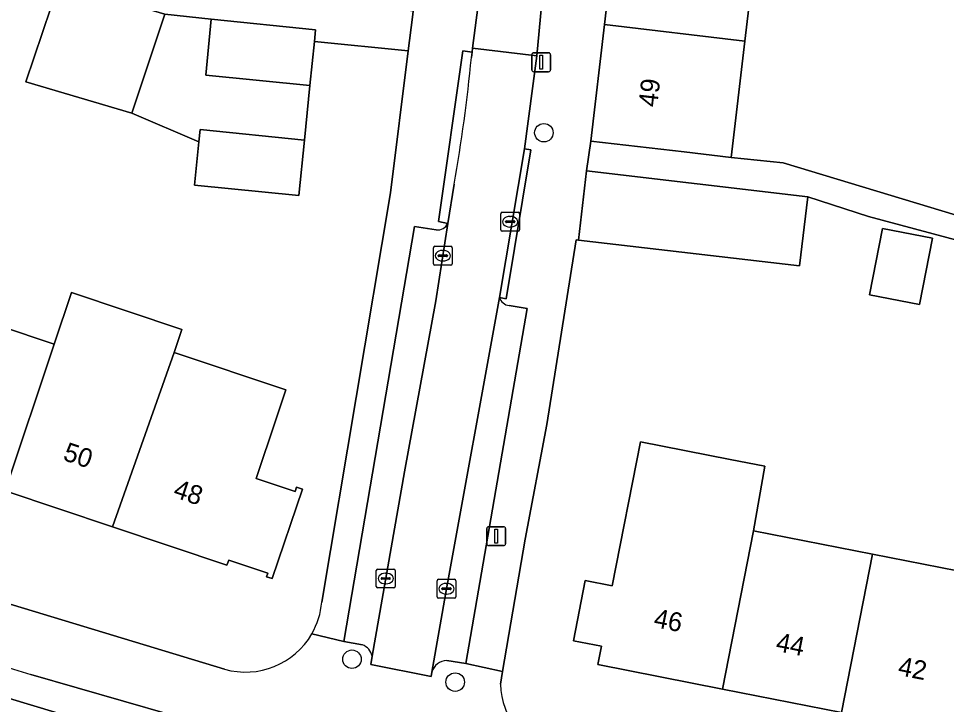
# Model space of a CAD drawing. Extents: x 161692 to 162379, y 380760 to 381678.
# Drawn here: x 162049.01 to 162098.13, y 380945.92 to 380982.23 of the extents above; entities that cross this region are included whole.
import ezdxf

# ---------------------------------------------------------------- set-up
doc = ezdxf.new("R2010")
doc.units = 0
for name, color, linetype in [('IMGEO_Boom', 7, 'Continuous'), ('IMGEO_Erf', 7, 'Continuous'), ('IMGEO_Kolk', 7, 'Continuous'), ('IMGEO_Lichtmast', 7, 'Continuous'), ('IMGEO_Pand', 7, 'Continuous'), ('IMGEO_Pand_nummerreeks', 7, 'Continuous'), ('IMGEO_Parkeervlak_open', 7, 'Continuous'), ('IMGEO_Rijbaan_lokaal_open', 7, 'Continuous'), ('IMGEO_Voetpad_open', 7, 'Continuous')]:
    doc.layers.add(name, color=color, linetype=linetype)

msp = doc.modelspace()

# ---------------------------------------------------------------- linework, layer by layer
at = {"layer": 'IMGEO_Boom'}
for centre in [(162076.818, 380976.189), (162066.662, 380948.318), (162072.124, 380947.104)]:
    msp.add_circle(centre, 0.489, dxfattribs=at)
at = {"layer": 'IMGEO_Erf'}
for points in [[(162108.948, 380996.227), (162092.107, 380998.166), (162091.414, 380992.247), (162092.261, 380992.148), (162091.592, 380986.443), (162088.137, 380986.847), (162087.458, 380981.041), (162086.737, 380974.878), (162089.487, 380974.589), (162100.749, 380971.183), (162102.141, 380971.158), (162102.669, 380975.748), (162102.837, 380975.728), (162102.984, 380975.711), (162103.382, 380979.175), (162103.236, 380979.192), (162103.592, 380982.285), (162107.294, 380981.859)], [(162094.057, 380967.607), (162094.745, 380971.12), (162097.388, 380970.603), (162096.7, 380967.089)]]:
    msp.add_lwpolyline(points, close=True, dxfattribs=at)
for points in [[(162058.561, 380975.708), (162055.003, 380977.223), (162049.4, 380978.891), (162051.158, 380984.129), (162042.064, 380986.765), (162028.946, 380990.739), (162028.64, 380987.79), (162028.341, 380984.905), (162028.036, 380981.959), (162022.566, 380982.526), (162022.872, 380985.472), (162023.171, 380988.357), (162023.436, 380990.915), (162015.772, 380991.71), (162013.002, 380966.811)], [(162065.061, 380951.346), (162068.692, 380973.013), (162069.64, 380980.521), (162064.673, 380981.023), (162064.437, 380978.687), (162064.146, 380975.802), (162063.848, 380972.857), (162058.33, 380973.414), (162058.561, 380975.708)], [(162132.879, 380959.696), (162133.289, 380963.379), (162133.292, 380963.402), (162128.302, 380963.957), (162127.875, 380960.276), (162121.451, 380961.021), (162118.709, 380961.339), (162119.137, 380965.021), (162094.009, 380971.754), (162090.784, 380972.802), (162090.355, 380969.134), (162078.65, 380970.503), (162078.529, 380970.519), (162076.983, 380960.751), (162075.837, 380954.674), (162074.633, 380947.67), (162074.517, 380946.993)], [(162045.148, 380966.92), (162050.899, 380964.99), (162051.819, 380967.732), (162057.652, 380965.775), (162057.243, 380964.561), (162063.159, 380962.576), (162062.646, 380961.048), (162061.584, 380957.882), (162063.652, 380957.188), (162063.731, 380957.425), (162064.034, 380957.323), (162062.444, 380952.582), (162062.14, 380952.683), (162062.203, 380952.872), (162060.135, 380953.565), (162060.043, 380953.29), (162053.992, 380955.32), (162048.296, 380957.232)], [(162016.411, 380962.617), (162029.526, 380957.667), (162046.576, 380951.828), (162059.92, 380947.792)], [(162092.574, 380945.498), (162086.277, 380946.738), (162079.678, 380948.037), (162079.861, 380949.008), (162078.391, 380949.288), (162079.005, 380952.476), (162080.435, 380952.204), (162081.93, 380959.823), (162086.682, 380958.89), (162088.516, 380958.53), (162087.919, 380955.109), (162094.217, 380953.873), (162100.51, 380952.638)]]:
    msp.add_lwpolyline(points, dxfattribs=at)
for centre, radius, start, end in [((162061.035, 380951.675), 4.04, 330.1077, 355.3238), ((162061.035, 380951.674), 4.039, 253.9792, 330.1192), ((162078.598, 380947.117), 4.083, 181.7446, 253.9573)]:
    msp.add_arc(centre, radius, start, end, dxfattribs=at)
at = {"layer": 'IMGEO_Kolk'}
for p, q in [((162074.535, 380971.051), (162074.535, 380971.903)), ((162074.61, 380971.977), (162075.462, 380971.977)), ((162075.536, 380971.903), (162075.536, 380971.051)), ((162074.794, 380971.471), (162074.794, 380971.483)), ((162075.232, 380971.434), (162074.834, 380971.434)), ((162074.837, 380971.52), (162075.235, 380971.52)), ((162075.023, 380971.757), (162075.048, 380971.757)), ((162075.278, 380971.483), (162075.278, 380971.471)), ((162075.462, 380970.977), (162074.61, 380970.977)), ((162075.046, 380971.197), (162075.021, 380971.197)), ((162070.968, 380969.252), (162070.968, 380970.104)), ((162071.043, 380970.178), (162071.895, 380970.178)), ((162071.456, 380969.958), (162071.481, 380969.958)), ((162071.969, 380970.104), (162071.969, 380969.252)), ((162071.227, 380969.672), (162071.227, 380969.684)), ((162071.665, 380969.635), (162071.267, 380969.635)), ((162071.27, 380969.721), (162071.668, 380969.721)), ((162071.479, 380969.398), (162071.454, 380969.398)), ((162071.711, 380969.684), (162071.711, 380969.672)), ((162071.895, 380969.178), (162071.043, 380969.178)), ((162067.949, 380952.164), (162067.949, 380953.016)), ((162068.024, 380953.09), (162068.876, 380953.09)), ((162068.437, 380952.87), (162068.462, 380952.87)), ((162068.95, 380953.016), (162068.95, 380952.164)), ((162068.208, 380952.584), (162068.208, 380952.596)), ((162068.646, 380952.547), (162068.248, 380952.547)), ((162068.251, 380952.633), (162068.649, 380952.633)), ((162068.46, 380952.31), (162068.435, 380952.31)), ((162068.692, 380952.596), (162068.692, 380952.584)), ((162071.162, 380951.622), (162071.162, 380952.474)), ((162071.237, 380952.548), (162072.089, 380952.548)), ((162071.65, 380952.328), (162071.675, 380952.328)), ((162072.163, 380952.474), (162072.163, 380951.622)), ((162068.876, 380952.09), (162068.024, 380952.09)), ((162071.421, 380952.042), (162071.421, 380952.054)), ((162071.859, 380952.005), (162071.461, 380952.005)), ((162071.464, 380952.091), (162071.862, 380952.091)), ((162071.673, 380951.768), (162071.648, 380951.768)), ((162071.905, 380952.054), (162071.905, 380952.042)), ((162072.089, 380951.548), (162071.237, 380951.548))]:
    msp.add_line(p, q, dxfattribs=at)
for points in [[(162074.535, 380971.051), (162074.535, 380971.903)], [(162074.61, 380971.977), (162075.462, 380971.977)], [(162075.536, 380971.903), (162075.536, 380971.051)], [(162075.462, 380970.977), (162074.61, 380970.977)], [(162070.968, 380969.252), (162070.968, 380970.104)], [(162071.043, 380970.178), (162071.895, 380970.178)], [(162071.969, 380970.104), (162071.969, 380969.252)], [(162071.895, 380969.178), (162071.043, 380969.178)], [(162067.949, 380952.164), (162067.949, 380953.016)], [(162068.024, 380953.09), (162068.876, 380953.09)], [(162068.95, 380953.016), (162068.95, 380952.164)], [(162071.162, 380951.622), (162071.162, 380952.474)], [(162071.237, 380952.548), (162072.089, 380952.548)], [(162072.163, 380952.474), (162072.163, 380951.622)], [(162068.876, 380952.09), (162068.024, 380952.09)], [(162072.089, 380951.548), (162071.237, 380951.548)]]:
    msp.add_lwpolyline(points, dxfattribs=at)
for centre, radius, start, end in [((162074.612, 380971.901), 0.0765, 91.552, 178.448), ((162074.612, 380971.901), 0.0765, 91.552, 178.448), ((162075.46, 380971.901), 0.0765, 1.552, 88.448), ((162075.46, 380971.901), 0.0765, 1.552, 88.448), ((162074.834, 380971.48), 0.0403, 85.8775, 175.7526), ((162074.831, 380971.47), 0.0366, 178.938, 274.7102), ((162075.235, 380971.477), 0.043, 264.8664, 352.4533), ((162075.239, 380971.482), 0.0386, 1.7309, 96.639), ((162074.612, 380971.053), 0.0765, 181.552, 268.448), ((162074.612, 380971.053), 0.0765, 181.552, 268.448), ((162075.46, 380971.053), 0.0765, 271.552, 358.448), ((162075.46, 380971.053), 0.0765, 271.552, 358.448), ((162071.045, 380970.102), 0.0765, 91.552, 178.448), ((162071.045, 380970.102), 0.0765, 91.552, 178.448), ((162071.893, 380970.102), 0.0765, 1.552, 88.448), ((162071.893, 380970.102), 0.0765, 1.552, 88.448), ((162071.267, 380969.681), 0.0403, 85.8775, 175.7526), ((162071.264, 380969.671), 0.0366, 178.938, 274.7102), ((162071.668, 380969.678), 0.043, 264.8664, 352.4533), ((162071.672, 380969.683), 0.0386, 1.7309, 96.639), ((162071.045, 380969.254), 0.0765, 181.552, 268.448), ((162071.045, 380969.254), 0.0765, 181.552, 268.448), ((162071.893, 380969.254), 0.0765, 271.552, 358.448), ((162071.893, 380969.254), 0.0765, 271.552, 358.448), ((162068.026, 380953.014), 0.0765, 91.552, 178.448), ((162068.026, 380953.014), 0.0765, 91.552, 178.448), ((162068.874, 380953.014), 0.0765, 1.552, 88.448), ((162068.874, 380953.014), 0.0765, 1.552, 88.448), ((162068.026, 380952.166), 0.0765, 181.552, 268.448), ((162068.026, 380952.166), 0.0765, 181.552, 268.448), ((162068.248, 380952.593), 0.0403, 85.8775, 175.7526), ((162068.245, 380952.583), 0.0366, 178.938, 274.7102), ((162068.649, 380952.59), 0.043, 264.8664, 352.4533), ((162068.653, 380952.595), 0.0386, 1.7309, 96.639), ((162068.874, 380952.166), 0.0765, 271.552, 358.448), ((162068.874, 380952.166), 0.0765, 271.552, 358.448), ((162071.239, 380952.472), 0.0765, 91.552, 178.448), ((162071.239, 380952.472), 0.0765, 91.552, 178.448), ((162072.087, 380952.472), 0.0765, 1.552, 88.448), ((162072.087, 380952.472), 0.0765, 1.552, 88.448), ((162071.461, 380952.051), 0.0403, 85.8775, 175.7526), ((162071.458, 380952.041), 0.0366, 178.938, 274.7102), ((162071.862, 380952.048), 0.043, 264.8664, 352.4533), ((162071.866, 380952.053), 0.0386, 1.7309, 96.639), ((162071.239, 380951.624), 0.0765, 181.552, 268.448), ((162071.239, 380951.624), 0.0765, 181.552, 268.448), ((162072.087, 380951.624), 0.0765, 271.552, 358.448), ((162072.087, 380951.624), 0.0765, 271.552, 358.448)]:
    msp.add_arc(centre, radius, start, end, dxfattribs=at)
for centre, major_axis, ratio, start_param, end_param in [((162075.022, 380971.477), (-0.387, 0.002), 0.722429, 4.712389, 7.853982), ((162075.047, 380971.477), (-0.39, 0.002), 0.717154, 1.570796, 4.712389), ((162071.455, 380969.678), (-0.387, 0.002), 0.722429, 4.712389, 7.853982), ((162071.48, 380969.678), (-0.39, 0.002), 0.717154, 1.570796, 4.712389), ((162068.436, 380952.59), (-0.387, 0.002), 0.722429, 4.712389, 7.853982), ((162068.461, 380952.59), (-0.39, 0.002), 0.717154, 1.570796, 4.712389), ((162071.649, 380952.048), (-0.387, 0.002), 0.722429, 4.712389, 7.853982), ((162071.674, 380952.048), (-0.39, 0.002), 0.717154, 1.570796, 4.712389)]:
    msp.add_ellipse(centre, major_axis=major_axis, ratio=ratio, start_param=start_param, end_param=end_param, dxfattribs=at)
at = {"layer": 'IMGEO_Lichtmast'}
for p, q in [((162076.18, 380979.521), (162076.18, 380980.321)), ((162076.18, 380980.321), (162076.18, 380979.521)), ((162076.28, 380980.421), (162077.07, 380980.421)), ((162077.07, 380980.421), (162076.28, 380980.421)), ((162077.17, 380980.321), (162077.17, 380979.521)), ((162077.17, 380979.521), (162077.17, 380980.321)), ((162077.07, 380979.421), (162076.28, 380979.421)), ((162076.28, 380979.421), (162077.07, 380979.421)), ((162073.797, 380954.429), (162073.797, 380955.229)), ((162073.797, 380955.229), (162073.797, 380954.429)), ((162073.897, 380955.329), (162074.687, 380955.329)), ((162074.687, 380955.329), (162073.897, 380955.329)), ((162074.787, 380955.229), (162074.787, 380954.429)), ((162074.787, 380954.429), (162074.787, 380955.229)), ((162074.687, 380954.329), (162073.897, 380954.329)), ((162073.897, 380954.329), (162074.687, 380954.329))]:
    msp.add_line(p, q, dxfattribs=at)
for points in [[(162076.6, 380980.296), (162076.75, 380980.296), (162076.75, 380979.546), (162076.6, 380979.546), (162076.6, 380980.296)], [(162074.217, 380955.204), (162074.367, 380955.204), (162074.367, 380954.454), (162074.217, 380954.454), (162074.217, 380955.204)]]:
    msp.add_lwpolyline(points, dxfattribs=at)
for centre, start, end in [((162076.28, 380980.321), 90, 180), ((162076.28, 380980.321), 90, 180), ((162077.07, 380980.321), 0, 90), ((162077.07, 380980.321), 360, 90), ((162076.28, 380979.521), 180, 270), ((162076.28, 380979.521), 180, 270), ((162077.07, 380979.521), 270, 0), ((162077.07, 380979.521), 270, 0), ((162073.897, 380955.229), 90, 180), ((162073.897, 380955.229), 90, 180), ((162074.687, 380955.229), 0, 90), ((162074.687, 380955.229), 360, 90), ((162073.897, 380954.429), 180, 270), ((162073.897, 380954.429), 180, 270), ((162074.687, 380954.429), 270, 0), ((162074.687, 380954.429), 270, 0)]:
    msp.add_arc(centre, 0.1, start, end, dxfattribs=at)
at = {"layer": 'IMGEO_Pand'}
for points in [[(162080.701, 380987.719), (162080.022, 380981.912), (162087.458, 380981.041), (162088.137, 380986.847)], [(162056.76, 380982.461), (162051.158, 380984.129), (162049.4, 380978.891), (162055.003, 380977.223)], [(162064.437, 380978.687), (162058.919, 380979.243), (162059.217, 380982.192), (162056.76, 380982.461), (162055.003, 380977.223), (162058.561, 380975.708), (162058.627, 380976.358), (162064.146, 380975.802)], [(162064.673, 380981.023), (162064.735, 380981.634), (162059.217, 380982.192), (162058.919, 380979.243), (162064.437, 380978.687)], [(162087.458, 380981.041), (162080.022, 380981.912), (162079.301, 380975.748), (162084.248, 380975.169), (162086.737, 380974.878)], [(162064.146, 380975.802), (162058.627, 380976.358), (162058.561, 380975.708), (162058.33, 380973.414), (162063.848, 380972.857)], [(162079.079, 380974.171), (162078.65, 380970.503), (162090.355, 380969.134), (162090.784, 380972.802)], [(162094.057, 380967.607), (162096.7, 380967.089), (162097.388, 380970.603), (162094.745, 380971.12)], [(162057.243, 380964.561), (162057.652, 380965.775), (162051.819, 380967.732), (162050.899, 380964.99), (162048.296, 380957.232), (162053.992, 380955.32)], [(162042.545, 380959.162), (162048.296, 380957.232), (162050.899, 380964.99), (162045.148, 380966.92)], [(162057.243, 380964.561), (162053.992, 380955.32), (162060.043, 380953.29), (162060.135, 380953.565), (162062.203, 380952.872), (162062.14, 380952.683), (162062.444, 380952.582), (162064.034, 380957.323), (162063.731, 380957.425), (162063.652, 380957.188), (162061.584, 380957.882), (162062.646, 380961.048), (162063.159, 380962.576)], [(162087.919, 380955.109), (162088.516, 380958.53), (162086.682, 380958.89), (162081.93, 380959.823), (162080.435, 380952.204), (162079.005, 380952.476), (162078.391, 380949.288), (162079.861, 380949.008), (162079.678, 380948.037), (162086.277, 380946.738)], [(162087.919, 380955.109), (162086.277, 380946.738), (162092.574, 380945.498), (162094.217, 380953.873)], [(162100.51, 380952.638), (162094.217, 380953.873), (162092.574, 380945.498), (162098.866, 380944.26)]]:
    msp.add_lwpolyline(points, close=True, dxfattribs=at)
at = {"layer": 'IMGEO_Parkeervlak_open'}
for points in [[(162067.731, 380948.487), (162069.441, 380958.238), (162071.092, 380967.289), (162071.74, 380971.386)], [(162071.12, 380971.046), (162069.977, 380971.232), (162066.23, 380949.256), (162067.221, 380949.081)], [(162074.463, 380967.458), (162071.663, 380952.048), (162070.893, 380947.639)], [(162075.941, 380966.884), (162074.977, 380967.038)], [(162071.68, 380948.246), (162072.696, 380948.097), (162075.941, 380966.884)], [(162012.438, 380958.632), (162018.278, 380956.309), (162034.3, 380950.52), (162053.339, 380944.791), (162061.904, 380942.435)], [(162061.683, 380942.988), (162061.918, 380943.985), (162049.658, 380947.516)]]:
    msp.add_lwpolyline(points, dxfattribs=at)
for centre, radius, start, end in [((162071.176, 380971.679), 0.636, 264.938, 332.5416), ((162075.069, 380967.675), 0.644, 199.7043, 261.7897), ((162192.94, 381422.171), 495.81, 251.44478, 253.20277), ((162066.88, 380948.273), 0.877, 14.1431, 67.1547), ((162071.681, 380947.431), 0.815, 90.0946, 165.1902)]:
    msp.add_arc(centre, radius, start, end, dxfattribs=at)
at = {"layer": 'IMGEO_Rijbaan_lokaal_open'}
msp.add_lwpolyline([(162076.701, 380982.915), (162073.39, 380983.299), (162073.33, 380982.818), (162073.049, 380980.658), (162076.444, 380980.264)], close=True, dxfattribs=at)
for points in [[(162074.463, 380967.458), (162075.791, 380975.337), (162076.444, 380980.264), (162073.049, 380980.658), (162073.02, 380980.445), (162072.983, 380980.173)], [(162072.069, 380973.47), (162071.74, 380971.386), (162071.092, 380967.289), (162069.441, 380958.238), (162067.731, 380948.487), (162067.651, 380948.033), (162070.851, 380947.398), (162070.893, 380947.639), (162071.663, 380952.048), (162074.463, 380967.458)], [(162101.679, 380932.917), (162084.553, 380936.527), (162073.615, 380939.265), (162072.471, 380939.575), (162063.01, 380942.135), (162062.2, 380942.354), (162061.904, 380942.435), (162053.339, 380944.791), (162034.3, 380950.52), (162018.278, 380956.309), (162012.438, 380958.632), (162010.753, 380953.818), (162022.315, 380949.277)]]:
    msp.add_lwpolyline(points, dxfattribs=at)
msp.add_arc((161990.005, 380988.074), 83.354, 349.9095, 354.56093, dxfattribs=at)
at = {"layer": 'IMGEO_Voetpad_open'}
for points in [[(162091.779, 381143.228), (162088.76, 381143.274), (162087.113, 381128.778), (162086.463, 381123.177), (162086.034, 381119.469), (162085.911, 381118.471), (162085.144, 381111.839), (162084.533, 381106.562), (162084.352, 381105.057), (162081.406, 381080.534), (162080.783, 381075.07), (162080.609, 381073.546), (162073.358, 381009.985), (162072.098, 381000), (162069.905, 380982.626), (162069.864, 380982.299), (162069.64, 380980.521), (162068.692, 380973.013), (162065.061, 380951.346)], [(162075.837, 380954.674), (162076.983, 380960.751), (162078.529, 380970.519), (162078.65, 380970.503), (162079.079, 380974.171), (162079.301, 380975.748), (162080.022, 380981.912), (162080.701, 380987.719), (162081.369, 380993.424), (162082.079, 380999.496), (162082.132, 381000), (162082.158, 381000.245), (162082.864, 381006.354), (162083.524, 381012.063), (162084.196, 381017.874)], [(162078.155, 380996.635), (162076.701, 380982.915), (162076.444, 380980.264), (162075.791, 380975.337), (162076.134, 380975.28), (162074.825, 380967.397), (162074.463, 380967.458)], [(162042.064, 380986.765), (162051.158, 380984.129), (162056.76, 380982.461), (162059.217, 380982.192), (162064.735, 380981.634), (162064.673, 380981.023), (162069.64, 380980.521), (162069.864, 380982.299), (162069.905, 380982.626), (162065.115, 380983.188), (162063.973, 380983.322), (162060.15, 380983.771), (162057.079, 380984.131), (162047.712, 380986.308)], [(162071.74, 380971.386), (162071.25, 380971.483), (162072.526, 380980.516), (162073.02, 380980.445), (162073.049, 380980.658), (162073.33, 380982.818), (162073.39, 380983.299), (162073.398, 380983.371)], [(162072.983, 380980.173), (162073.02, 380980.445), (162072.526, 380980.516), (162071.25, 380971.483), (162071.74, 380971.386), (162072.069, 380973.47)], [(162100.749, 380971.183), (162089.487, 380974.589), (162086.737, 380974.878), (162084.248, 380975.169), (162079.301, 380975.748), (162079.079, 380974.171), (162090.784, 380972.802), (162094.009, 380971.754), (162119.137, 380965.021)], [(162064.537, 380949.662), (162066.23, 380949.256), (162069.977, 380971.232), (162071.12, 380971.046)], [(162074.977, 380967.038), (162075.941, 380966.884), (162072.696, 380948.097), (162074.633, 380947.67), (162075.837, 380954.674)], [(162059.92, 380947.792), (162046.576, 380951.828), (162029.526, 380957.667), (162016.411, 380962.617), (162015.272, 380962.845), (162008.182, 380964.946), (162008.121, 380964.42)], [(162067.221, 380949.081), (162066.23, 380949.256), (162064.537, 380949.662)], [(162067.651, 380948.033), (162067.731, 380948.487)], [(162074.517, 380946.993), (162074.633, 380947.67), (162072.696, 380948.097), (162071.68, 380948.246)], [(162070.893, 380947.639), (162070.851, 380947.398), (162067.651, 380948.033)], [(162049.658, 380947.516), (162061.918, 380943.985), (162061.683, 380942.988)]]:
    msp.add_lwpolyline(points, dxfattribs=at)
msp.add_lwpolyline([(162076.134, 380975.28), (162075.791, 380975.337), (162074.463, 380967.458), (162074.825, 380967.397)], close=True, dxfattribs=at)
for centre, radius, start, end in [((161990.005, 380988.074), 83.354, 349.9095, 354.56093), ((162071.176, 380971.679), 0.636, 264.938, 332.5416), ((162075.069, 380967.675), 0.644, 199.7043, 261.7897), ((162192.94, 381422.171), 495.81, 251.44478, 253.20277), ((162061.035, 380951.675), 4.04, 330.1077, 355.3238), ((162061.035, 380951.674), 4.039, 253.9792, 330.1192), ((162066.88, 380948.273), 0.877, 14.1431, 67.1547), ((162071.681, 380947.431), 0.815, 90.0946, 165.1902), ((162078.598, 380947.117), 4.083, 181.7446, 253.9573)]:
    msp.add_arc(centre, radius, start, end, dxfattribs=at)

# ---------------------------------------------------------------- texts
at = {"layer": 'IMGEO_Pand_nummerreeks'}
for s, rotation, p in [('49', 83.328, (162082.811, 380977.515)), ('50', 341.4502, (162051.311, 380958.878)), ('48', 341.4502, (162057.146, 380956.92)), ('46', 348.8638, (162082.585, 380950.033)), ('44', 348.8638, (162089.05, 380948.761)), ('42', 348.8617, (162095.513, 380947.488))]:
    msp.add_text(s, height=1, rotation=rotation, dxfattribs=at).set_placement(p)

doc.saveas('drawing.dxf')
